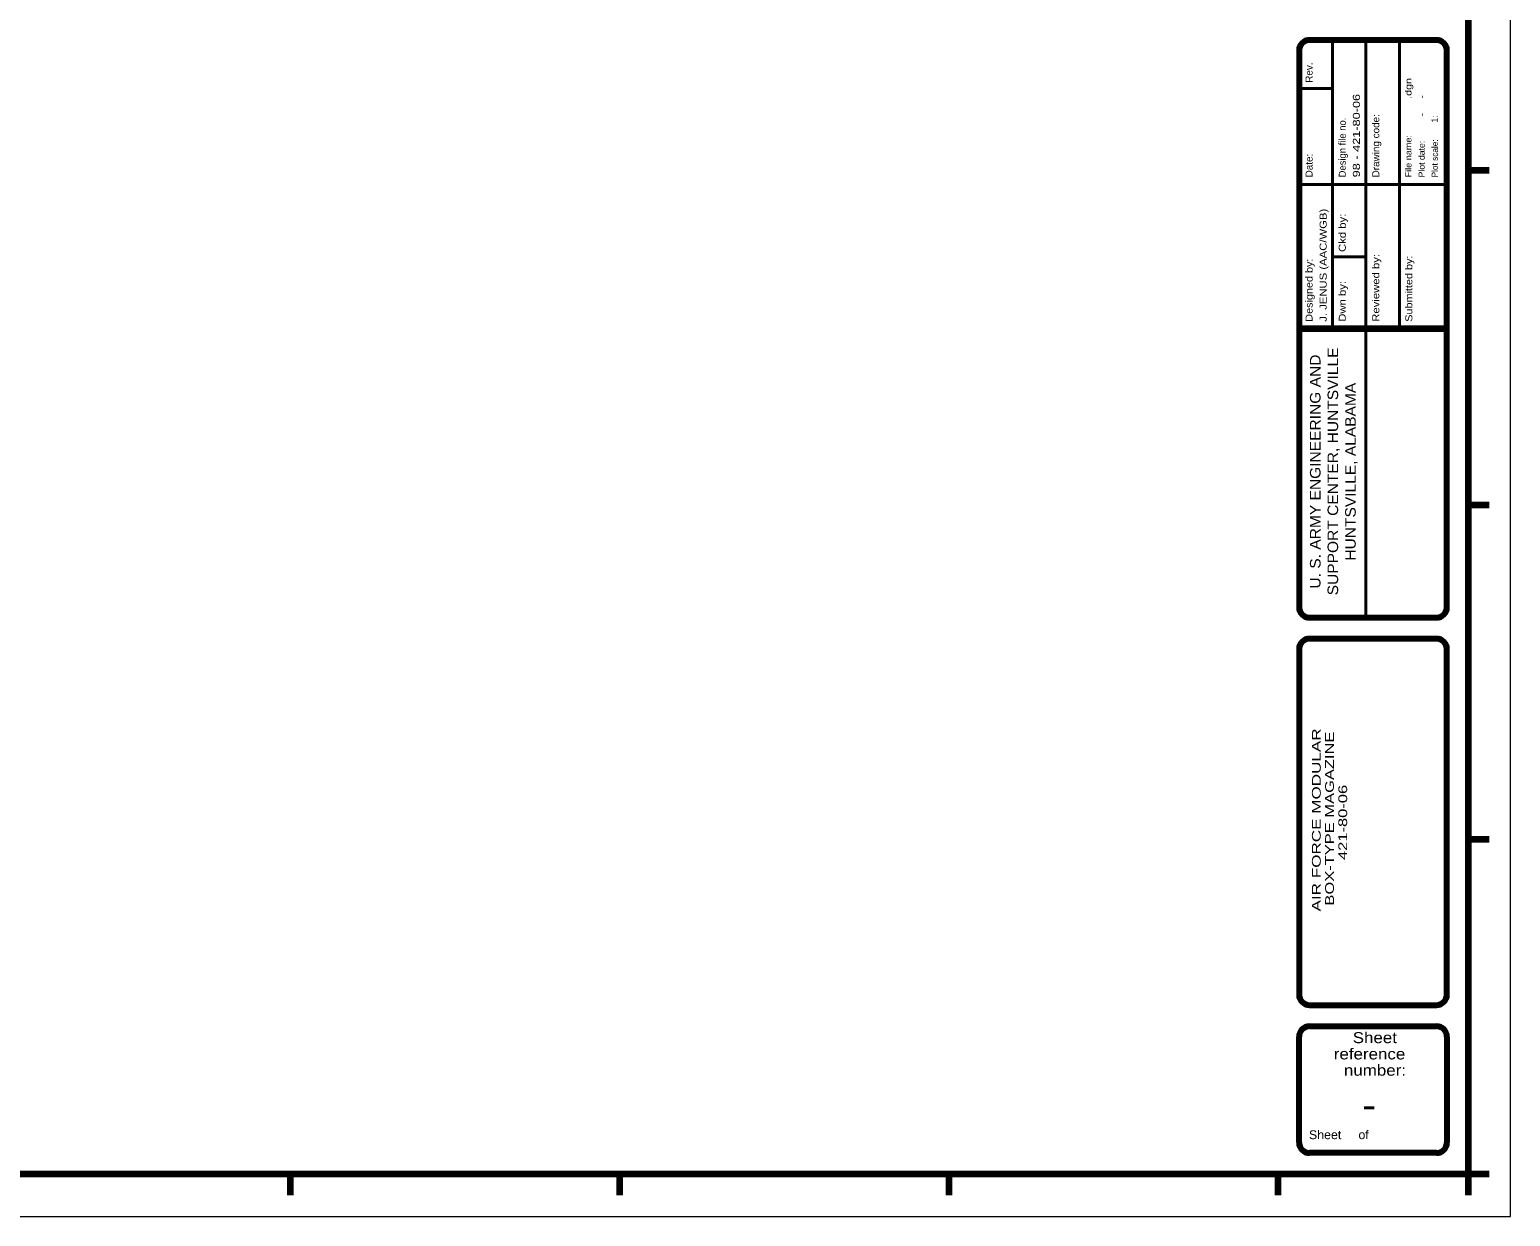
# Model space of a CAD drawing. Extents: x -202666 to -201825, y -108963 to -108369.
# Drawn here: x -202245.6 to -201825.1, y -108963.4 to -108626.4 of the extents above; entities that cross this region are included whole.
import ezdxf
from ezdxf.enums import TextEntityAlignment as Align

# ---------------------------------------------------------------- set-up
doc = ezdxf.new("R2010")
doc.units = 0
doc.header["$LTSCALE"] = 0.8
doc.layers.add('1', color=7, linetype='Continuous', lineweight=35)
doc.layers.add('3', color=7, linetype='Continuous')

msp = doc.modelspace()

# ---------------------------------------------------------------- linework, layer by layer
at = {"layer": '1', "lineweight": 80}
for p, q in [((-201846.116, -108629.424), (-201882.116, -108629.424)), ((-201885.116, -108632.424), (-201885.116, -108790.424)), ((-201843.116, -108790.424), (-201843.116, -108632.424)), ((-201882.116, -108793.424), (-201846.116, -108793.424)), ((-201846.116, -108799.424), (-201882.116, -108799.424)), ((-201885.116, -108802.424), (-201885.116, -108900.444)), ((-201843.116, -108900.444), (-201843.116, -108802.424)), ((-201882.116, -108903.444), (-201846.116, -108903.444)), ((-201882.113, -108909.444), (-201846.113, -108909.444)), ((-201885.113, -108942.444), (-201885.113, -108912.444)), ((-201843.113, -108912.444), (-201843.113, -108942.444)), ((-201846.113, -108945.444), (-201882.113, -108945.444))]:
    msp.add_line(p, q, dxfattribs=at)
at = {"layer": '1', "lineweight": 40}
for p, q in [((-201875.616, -108629.424), (-201875.616, -108711.424)), ((-201856.616, -108629.424), (-201856.616, -108711.424)), ((-201885.056, -108643.184), (-201875.616, -108643.184)), ((-201843.116, -108670.424), (-201885.116, -108670.424)), ((-201875.616, -108690.924), (-201866.116, -108690.924))]:
    msp.add_line(p, q, dxfattribs=at)
at = {"layer": '1', "lineweight": 90}
for p, q in [((-201831.113, -108666.444), (-201837.113, -108666.444)), ((-201843.116, -108711.424), (-201885.116, -108711.424)), ((-201831.113, -108761.444), (-201837.113, -108761.444)), ((-201831.113, -108856.444), (-201837.113, -108856.444)), ((-202171.613, -108951.444), (-202171.613, -108957.444)), ((-202078.113, -108951.444), (-202078.113, -108957.444)), ((-201984.613, -108951.444), (-201984.613, -108957.444)), ((-201891.113, -108951.444), (-201891.113, -108957.444)), ((-201831.113, -108951.444), (-201837.113, -108951.444))]:
    msp.add_line(p, q, dxfattribs=at)
at = {"layer": '1', "lineweight": 13}
msp.add_lwpolyline([(-202666.113, -108963.444), (-201825.113, -108963.444), (-201825.113, -108369.444), (-202666.113, -108369.444)], close=True, dxfattribs=at)
at = {"layer": '1', "lineweight": 90}
for points in [[(-201837.113, -108375.444), (-201837.113, -108381.444), (-201837.113, -108951.444), (-201837.113, -108957.444)], [(-201837.113, -108951.444), (-201891.113, -108951.444), (-202639.113, -108951.444)]]:
    msp.add_lwpolyline(points, dxfattribs=at)
at = {"layer": '1', "lineweight": 40}
msp.add_lwpolyline([(-201866.116, -108629.424), (-201866.116, -108711.424), (-201866.116, -108793.424)], dxfattribs=at)
at = {"layer": '1', "lineweight": 80}
for centre, start, end in [((-201882.116, -108632.424), 90, 180), ((-201846.116, -108632.424), 0, 90), ((-201882.116, -108790.424), 180, 270), ((-201846.116, -108790.424), 270, 0), ((-201882.116, -108802.424), 90, 180), ((-201846.116, -108802.424), 0, 90), ((-201882.116, -108900.444), 180, 270), ((-201846.116, -108900.444), 270, 0), ((-201882.113, -108912.444), 90, 180), ((-201846.113, -108912.444), 0, 90), ((-201882.113, -108942.444), 180, 270), ((-201846.113, -108942.444), 270, 0)]:
    msp.add_arc(centre, 3, start, end, dxfattribs=at)

# ---------------------------------------------------------------- texts
at = {"layer": '1'}
for s, height, width, p in [('Rev.', 2, 1.05, (-201881.286, -108641.534)), ('98 - 421-80-06    ', 2, 1.35, (-201867.846, -108668.394)), ('Drawing code:     ', 2, 1.05, (-201862.346, -108668.404)), ('File name:', 1.75, 1.1, (-201853.205, -108668.404)), ('Plot date:', 1.75, 1.05, (-201849.455, -108668.404)), ('Date:', 2, 1.05, (-201881.286, -108668.404)), ('Ckd by:', 2, 1.2, (-201871.846, -108689.594)), ('Reviewed by:', 2, 1.2, (-201862.346, -108709.404)), ('Designed by:', 2, 1.15, (-201881.286, -108709.404)), ('Submitted by:', 2, 1.15, (-201852.956, -108709.404)), ('Dwn by:', 2, 1.2, (-201871.846, -108709.404))]:
    msp.add_text(s, height=height, rotation=90, dxfattribs=dict(at, width=width)).set_placement(p)
for s, height, p in [('Design file no.   ', 2, (-201871.846, -108668.394)), ('Plot scale:', 1.75, (-201845.705, -108668.404))]:
    msp.add_text(s, height=height, rotation=90, dxfattribs=at).set_placement(p)
for s, height, width, p in [('U. S. ARMY ENGINEERING AND', 3, 1.1, (-201879.028, -108751.9375)), ('SUPPORT CENTER, HUNTSVILLE', 3, 1.1, (-201874.028, -108751.902)), ('HUNTSVILLE, ALABAMA', 3, 1.1, (-201869.029, -108751.9855)), ('           AIR FORCE MODULAR            ', 2.5, 1.45, (-201878.965, -108850.184)), ('           BOX-TYPE MAGAZINE            ', 2.5, 1.4, (-201875.215, -108849.8265)), ('               421-80-06                ', 2.5, 1.4, (-201871.465, -108850.929))]:
    msp.add_text(s, height=height, rotation=90, dxfattribs=dict(at, width=width)).set_placement(p, align=Align.CENTER)
at = {"layer": '1', "width": 1.15}
for s, p in [('Sheet', (-201863.6045, -108914.25)), ('reference', (-201865.1055, -108918.875)), ('number:', (-201863.568, -108923.5))]:
    msp.add_text(s, height=3.125, dxfattribs=at).set_placement(p, align=Align.CENTER)
at = {"layer": '3'}
for s, height, width, p in [('        .dgn', 1.75, 1.3, (-201853.205, -108652.878)), ('   -     -   ', 1.75, 1.25, (-201849.455, -108653.509)), ('J. JENUS (AAC/WGB) ', 2, 1.2, (-201877.286, -108709.404))]:
    msp.add_text(s, height=height, rotation=90, dxfattribs=dict(at, width=width)).set_placement(p)
msp.add_text('1:    ', height=1.75, rotation=90, dxfattribs=at).set_placement((-201845.768, -108652.814))
at = {"layer": '3', "width": 1.2}
msp.add_text('  -   ', height=7.5, dxfattribs=at).set_placement((-201863.5165, -108935.479), align=Align.CENTER)
at = {"layer": '3', "width": 1.05}
msp.add_text('Sheet     of    ', height=2.5, dxfattribs=at).set_placement((-201882.309, -108941.512))

doc.saveas('drawing.dxf')
